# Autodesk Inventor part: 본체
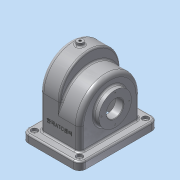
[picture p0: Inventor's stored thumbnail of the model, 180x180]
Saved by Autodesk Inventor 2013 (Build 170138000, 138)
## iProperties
Created: 2017-11
Part Number: 본체
Material: 알루미늄 6061
Document SubType Name: Modeling
Designer: Administrator
Density: 2.71 g/cm^3
Mass: 1079.49 g
Surface Area: 1182.07 cm^2
Volume: 398.334 cm^3
Author: Administrator
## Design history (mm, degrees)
sketch "스케치1"
  geometry: 1 further point
sketch "스케치2"
  geometry: L1 (-58, 0)-(58, 0); L2 (58, 0)-(58, 80); L3 (58, 80)-(-58, 80); L4 (-58, 80)-(-58, 0); A1 r 58 centre (0, 80) between (58, 80) and (-58, 80); 2 further points
  constraints: 8 end point, 2 parallel, 2 point on circle, 2 tangent, 1 centre point, 1 coincident, 1 horizontal, 1 midpoint, 1 perpendicular
  dimensions: "d0" = 80 distance of L3.end L1.start; "d2" = 116 distance of L2.end L3.end; "d3" = 58 radius of A1 (derived)
extrude "돌출1" new body sketch "스케치2" distance "d4" = 38; taper "d5" = 0 deg
sketch "스케치3"
  geometry: L1 (-80, -58)-(0, -58) reference; L2 (0, -58)-(0, 58) reference; L3 (0, 58)-(-80, 58) reference; L4 (0, -58)-(-57, -58); L5 (-57, -58)-(-57, 58); L6 (-57, 58)-(0, 58); L7 (0, 58)-(0, -58); A1 r 58 centre (-80, 0) between (-80, 58) and (-80, -58) reference; A2 r 58 centre (-57, 0) between (-57, 58) and (-57, -58); 2 further points
  constraints: 8 end point, 2 parallel, 2 point on circle, 1 centre point, 1 coincident, 1 horizontal, 1 midpoint, 1 perpendicular, 1 point on line
  dimensions: "d6" = 57 distance of L1.end L4.end; "d50" = 58 radius of A2 (derived)
extrude "돌출2" join sketch "스케치3" distance "d8" = 38; taper "d9" = 0 deg
feature "쉘1" dims "d10" = 5
sketch "스케치4"
  geometry: C1 r 37.5 at (65, 0); 1 further point
  constraints: 1 centre point
  dimensions: "d11" = 75 diameter of C1; "d12" = 65 distance of C1.centre point (0, 0)
extrude "돌출3" join sketch "스케치4" distance "d13" = 9; taper "d14" = 0 deg
sketch "스케치5"
  geometry: C1 r 31 at (-65, 0); 1 further point
  constraints: 1 centre point
  dimensions: "d15" = 62 diameter of C1; "d17" = 65 distance of point (0, 0) C1.centre
extrude "돌출4" join sketch "스케치5" distance "d18" = 10; taper "d19" = 0 deg
sketch "스케치6"
  geometry: C1 r 37.5 at (0, 0) reference; A1 r 29 centre (0, 0) between (29, 0) and (0, 29); 3 further points
  constraints: 4 point on circle, 1 centre point, 1 coincident
  dimensions: "d20" = 58 diameter of A1
hole "구멍1" sketch "스케치6" at (29, 0), (0, -29), (0, 29), (-29, 0) diameter "d21" = 2.459; stored, may be unused: countersink angle "d25" = 90 deg, drill point angle "d27" = 118 deg; dims "d22" = 6, "d23" = 4, "d24" = 2, "d26" = 8
sketch "스케치7"
  geometry: C1 r 37.5 at (0, 0) reference; C2 r 16 at (0, 0); 1 further point
  constraints: 1 centre point, 1 coincident
  dimensions: "d28" = 32 diameter of C2
extrude "돌출5" cut sketch "스케치7" stored distance "d30" = 10; taper "d31" = 0 deg
sketch "스케치8"
  geometry: C1 r 16 at (0, 0) reference; A1 r 26 centre (0, 0) between (26, 0) and (0, 26); 3 further points
  constraints: 4 point on circle, 1 centre point, 1 coincident
  dimensions: "d32" = 52 diameter of A1
hole "구멍2" sketch "스케치8" at (0, -26), (-26, 0), (0, 26), (26, 0) diameter "d33" = 2.459; stored, may be unused: countersink angle "d37" = 90 deg, drill point angle "d39" = 118 deg; dims "d34" = 6, "d35" = 4, "d36" = 2, "d38" = 8
sketch "스케치9"
  geometry: L1 (-38, 58)-(-38, -58) reference; L2 (0, 58)-(-38, 58) reference; L3 (0, 58)-(38, 58) reference; L4 (38, -58)-(38, 58) reference; L5 (0, -58)-(38, -58) reference; L6 (0, -58)-(-38, -58) reference; L7 (-55, 75)-(55, 75); L8 (55, 75)-(55, -75); L9 (55, -75)-(-55, -75); L10 (-55, -75)-(-55, 75); 3 further points
  constraints: 8 end point, 2 midpoint, 2 parallel, 1 horizontal, 1 horizontal alignment, 1 perpendicular, 1 vertical alignment
  dimensions: "d40" = 110 distance of L7.start L7.end; "d42" = 150 distance of L7.end L8.end
extrude "돌출6" join sketch "스케치9" distance "d43" = 15; taper "d44" = 0 deg
fillet "모깎기2" dims "d46" = 8
fillet "모깎기3" dims "d47" = 3
fillet "모깎기4" dims "d48" = 3
chamfer "모따기1" distance "d51" = 1; stored, may be unused: second distance "d52" = 2, angle "d53" = 45 deg
fillet "모깎기5" dims "d54" = 3
fillet "모깎기6" dims "d55" = 12
hole "구멍3" diameter "d58" = 5; stored, may be unused: countersink angle "d62" = 90 deg, drill point angle "d64" = 118 deg; dims "d56" = 10, "d57" = 10, "d59" = 6, "d60" = 12, "d61" = 5, "d63" = 8
hole "구멍4" diameter "d67" = 5; stored, may be unused: countersink angle "d71" = 90 deg, drill point angle "d73" = 118 deg; dims "d65" = 10, "d66" = 10, "d68" = 6, "d69" = 12, "d70" = 5, "d72" = 8
hole "구멍5" diameter "d76" = 5; stored, may be unused: countersink angle "d80" = 90 deg, drill point angle "d82" = 118 deg; dims "d74" = 10, "d75" = 10, "d77" = 6, "d78" = 12, "d79" = 5, "d81" = 8
hole "구멍6" diameter "d85" = 5; stored, may be unused: countersink angle "d89" = 90 deg, drill point angle "d91" = 118 deg; dims "d83" = 10, "d84" = 10, "d86" = 6, "d87" = 12, "d88" = 5, "d90" = 8
fillet "모깎기7" dims "d92" = 3
fillet "모깎기8" dims "d93" = 3
node "작업 평면1"
sketch "스케치10"
  geometry: L1 (-38, -50)-(-38, 50) reference; L2 (43, 75)-(-43, 75) reference; C1 r 6 at (-19, 0); 1 further point
  constraints: 1 centre point
  dimensions: "d95" = 12 diameter of C1; "d97" = 19 distance from line of C1.centre L1; "d98" = 75 distance from line of C1.centre L2
extrude "돌출7" join sketch "스케치10" stored distance "d99" = 15; taper "d100" = 0 deg
fillet "모깎기9" dims "d101" = 3
hole "구멍7" diameter "d104" = 4.459; stored, may be unused: countersink angle "d108" = 90 deg, drill point angle "d110" = 118 deg; dims "d102" = 10, "d103" = 10, "d105" = 6, "d106" = 12, "d107" = 5, "d109" = 8
chamfer "모따기2" distance "d111" = 1; stored, may be unused: second distance "d112" = 2, angle "d113" = 45 deg
sketch "스케치11"
  geometry: L1 (-35, 23)-(-35, -39) reference; L2 (-40, -57)-(-52, -57) reference; 2 further points
  constraints: 1 other
  dimensions: "d114" = 38 distance from line of L1 point (3, -17); "d115" = 40 distance from line of point (3, -17) L2
feature "엠보싱1" sketch "스케치11" dims "d116" = 0.5, "d117" = 0
fillet "모깎기10" dims "d118" = 3
fillet "모깎기11" dims "d119" = 3
node "솔리드1"
node "투영된 루프1"
other parameters: "d94" = 144
